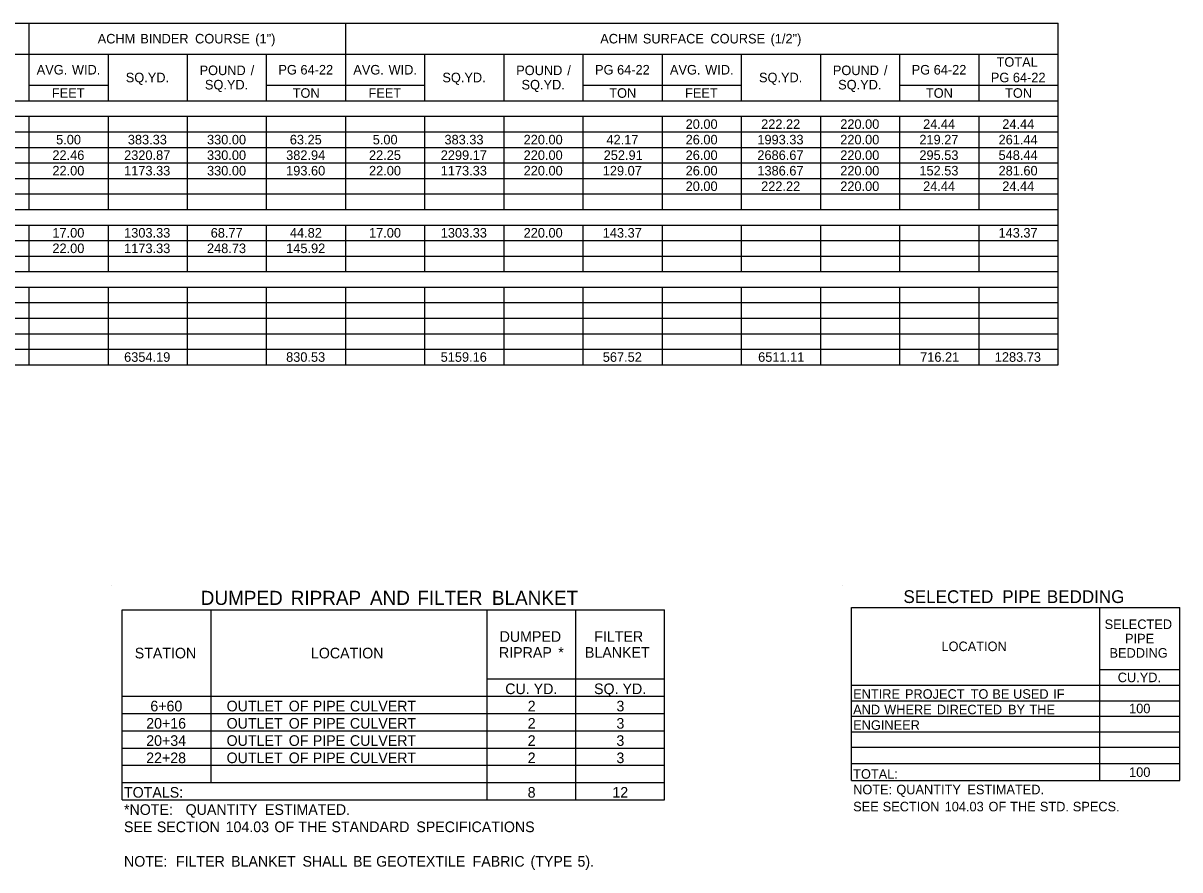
# Model space of a CAD drawing. Extents: x 1940653 to 1945779, y 534266 to 535271.
# Drawn here: x 1943159 to 1943813, y 534744 to 535222 of the extents above; entities that cross this region are included whole.
import ezdxf

# ---------------------------------------------------------------- set-up
doc = ezdxf.new("R2010")
doc.units = 0
doc.layers.add('Default', color=7, linetype='Continuous')
doc.layers.add('R_Logo', color=7, linetype='Continuous')

msp = doc.modelspace()

# ---------------------------------------------------------------- linework, layer by layer
at = {"layer": 'Default'}
for p, q in [((1942444.79, 535222.25), (1943743.93, 535222.25)), ((1943162.15, 535178.37), (1943162.15, 535222.25)), ((1943341.16, 535204.7), (1943341.16, 535222.25)), ((1943341.16, 535178.37), (1943341.16, 535222.25)), ((1943743.93, 535037.97), (1943743.93, 535222.25)), ((1943743.93, 535029.2), (1943743.93, 535222.25)), ((1942759.38, 535204.7), (1943743.93, 535204.7)), ((1943206.9, 535178.37), (1943206.9, 535204.7)), ((1943251.66, 535178.37), (1943251.66, 535204.7)), ((1943296.41, 535178.37), (1943296.41, 535204.7)), ((1943385.91, 535204.7), (1943430.67, 535204.7)), ((1943385.91, 535178.37), (1943385.91, 535204.7)), ((1943430.67, 535178.37), (1943430.67, 535204.7)), ((1943475.42, 535178.37), (1943475.42, 535204.7)), ((1943520.17, 535178.37), (1943520.17, 535204.7)), ((1943564.92, 535204.7), (1943609.68, 535204.7)), ((1943564.92, 535178.37), (1943564.92, 535204.7)), ((1943609.68, 535178.37), (1943609.68, 535204.7)), ((1943654.43, 535178.37), (1943654.43, 535204.7)), ((1943699.18, 535178.37), (1943699.18, 535204.7)), ((1943162.15, 535187.15), (1943206.9, 535187.15)), ((1943206.9, 535178.37), (1943206.9, 535187.15)), ((1943296.41, 535187.15), (1943385.91, 535187.15)), ((1943341.16, 535178.37), (1943341.16, 535187.15)), ((1943385.91, 535178.37), (1943385.91, 535187.15)), ((1943475.42, 535187.15), (1943564.92, 535187.15)), ((1943520.17, 535178.37), (1943520.17, 535187.15)), ((1943564.92, 535178.37), (1943564.92, 535187.15)), ((1943654.43, 535187.15), (1943743.93, 535187.15)), ((1942444.79, 535178.37), (1943743.93, 535178.37)), ((1943072.65, 535178.37), (1943206.9, 535178.37)), ((1943206.9, 535178.37), (1943385.91, 535178.37)), ((1943385.91, 535178.37), (1943564.92, 535178.37)), ((1943564.92, 535178.37), (1943743.93, 535178.37)), ((1942444.79, 535169.6), (1943743.93, 535169.6)), ((1943162.15, 535116.95), (1943162.15, 535169.6)), ((1943162.15, 535116.95), (1943162.15, 535169.6)), ((1943206.9, 535116.95), (1943206.9, 535169.6)), ((1943206.9, 535116.95), (1943206.9, 535169.6)), ((1943251.66, 535116.95), (1943251.66, 535169.6)), ((1943251.66, 535116.95), (1943251.66, 535169.6)), ((1943296.41, 535116.95), (1943296.41, 535169.6)), ((1943296.41, 535116.95), (1943296.41, 535169.6)), ((1943341.16, 535116.95), (1943341.16, 535169.6)), ((1943341.16, 535116.95), (1943341.16, 535169.6)), ((1943385.91, 535116.95), (1943385.91, 535169.6)), ((1943385.91, 535116.95), (1943385.91, 535169.6)), ((1943430.67, 535116.95), (1943430.67, 535169.6)), ((1943430.67, 535116.95), (1943430.67, 535169.6)), ((1943475.42, 535116.95), (1943475.42, 535169.6)), ((1943475.42, 535116.95), (1943475.42, 535169.6)), ((1943520.17, 535116.95), (1943520.17, 535169.6)), ((1943520.17, 535116.95), (1943520.17, 535169.6)), ((1943564.92, 535116.95), (1943564.92, 535169.6)), ((1943564.92, 535116.95), (1943564.92, 535169.6)), ((1943609.68, 535116.95), (1943609.68, 535169.6)), ((1943609.68, 535116.95), (1943609.68, 535169.6)), ((1943654.43, 535116.95), (1943654.43, 535169.6)), ((1943654.43, 535116.95), (1943654.43, 535169.6)), ((1943699.18, 535116.95), (1943699.18, 535169.6)), ((1943699.18, 535116.95), (1943699.18, 535169.6)), ((1942444.79, 535160.82), (1943743.93, 535160.82)), ((1942444.79, 535152.05), (1943743.93, 535152.05)), ((1942444.79, 535143.27), (1943743.93, 535143.27)), ((1942444.79, 535134.5), (1943743.93, 535134.5)), ((1942444.79, 535125.72), (1943743.93, 535125.72)), ((1942444.79, 535116.95), (1943743.93, 535116.95)), ((1943027.89, 535116.95), (1943162.15, 535116.95)), ((1943162.15, 535116.95), (1943564.92, 535116.95)), ((1943564.92, 535116.95), (1943609.68, 535116.95)), ((1943609.68, 535116.95), (1943699.18, 535116.95)), ((1943699.18, 535116.95), (1943743.93, 535116.95)), ((1942444.79, 535108.17), (1943743.93, 535108.17)), ((1943162.15, 535081.85), (1943162.15, 535108.17)), ((1943162.15, 535081.85), (1943162.15, 535108.17)), ((1943206.9, 535081.85), (1943206.9, 535108.17)), ((1943206.9, 535081.85), (1943206.9, 535108.17)), ((1943251.66, 535081.85), (1943251.66, 535108.17)), ((1943251.66, 535081.85), (1943251.66, 535108.17)), ((1943296.41, 535081.85), (1943296.41, 535108.17)), ((1943296.41, 535081.85), (1943296.41, 535108.17)), ((1943341.16, 535081.85), (1943341.16, 535108.17)), ((1943341.16, 535081.85), (1943341.16, 535108.17)), ((1943385.91, 535081.85), (1943385.91, 535108.17)), ((1943385.91, 535081.85), (1943385.91, 535108.17)), ((1943430.67, 535081.85), (1943430.67, 535108.17)), ((1943430.67, 535081.85), (1943430.67, 535108.17)), ((1943475.42, 535081.85), (1943475.42, 535108.17)), ((1943475.42, 535081.85), (1943475.42, 535108.17)), ((1943520.17, 535081.85), (1943520.17, 535108.17)), ((1943520.17, 535081.85), (1943520.17, 535108.17)), ((1943564.92, 535081.85), (1943564.92, 535108.17)), ((1943564.92, 535081.85), (1943564.92, 535108.17)), ((1943609.68, 535081.85), (1943609.68, 535108.17)), ((1943609.68, 535081.85), (1943609.68, 535108.17)), ((1943654.43, 535081.85), (1943654.43, 535108.17)), ((1943654.43, 535081.85), (1943654.43, 535108.17)), ((1943699.18, 535081.85), (1943699.18, 535108.17)), ((1943699.18, 535081.85), (1943699.18, 535108.17)), ((1942444.79, 535099.4), (1943743.93, 535099.4)), ((1942444.79, 535090.62), (1943743.93, 535090.62)), ((1942444.79, 535081.85), (1943743.93, 535081.85)), ((1943117.4, 535081.85), (1943564.92, 535081.85)), ((1943564.92, 535081.85), (1943609.68, 535081.85)), ((1943609.68, 535081.85), (1943699.18, 535081.85)), ((1943699.18, 535081.85), (1943743.93, 535081.85)), ((1942444.79, 535073.07), (1943743.93, 535073.07)), ((1943162.15, 535029.2), (1943162.15, 535073.07)), ((1943162.15, 535029.2), (1943162.15, 535073.07)), ((1943206.9, 535029.2), (1943206.9, 535073.07)), ((1943206.9, 535029.2), (1943206.9, 535073.07)), ((1943251.66, 535029.2), (1943251.66, 535073.07)), ((1943251.66, 535029.2), (1943251.66, 535073.07)), ((1943296.41, 535029.2), (1943296.41, 535073.07)), ((1943296.41, 535029.2), (1943296.41, 535073.07)), ((1943341.16, 535029.2), (1943341.16, 535073.07)), ((1943341.16, 535029.2), (1943341.16, 535073.07)), ((1943385.91, 535029.2), (1943385.91, 535073.07)), ((1943385.91, 535029.2), (1943385.91, 535073.07)), ((1943430.67, 535029.2), (1943430.67, 535073.07)), ((1943430.67, 535029.2), (1943430.67, 535073.07)), ((1943475.42, 535029.2), (1943475.42, 535073.07)), ((1943475.42, 535029.2), (1943475.42, 535073.07)), ((1943520.17, 535029.2), (1943520.17, 535073.07)), ((1943520.17, 535029.2), (1943520.17, 535073.07)), ((1943564.92, 535029.2), (1943564.92, 535073.07)), ((1943564.92, 535029.2), (1943564.92, 535073.07)), ((1943609.68, 535029.2), (1943609.68, 535073.07)), ((1943609.68, 535029.2), (1943609.68, 535073.07)), ((1943654.43, 535029.2), (1943654.43, 535073.07)), ((1943654.43, 535029.2), (1943654.43, 535073.07)), ((1943699.18, 535029.2), (1943699.18, 535073.07)), ((1943699.18, 535029.2), (1943699.18, 535073.07)), ((1942444.79, 535064.3), (1943743.93, 535064.3)), ((1942444.79, 535055.52), (1943743.93, 535055.52)), ((1942444.79, 535046.75), (1943743.93, 535046.75)), ((1942444.79, 535037.97), (1943743.93, 535037.97)), ((1942444.79, 535029.2), (1943743.93, 535029.2)), ((1943214.78, 534890.65), (1943521.42, 534890.65)), ((1943214.78, 534783.4), (1943214.78, 534890.65)), ((1943214.78, 534783.4), (1943214.78, 534890.65)), ((1943264.99, 534793.15), (1943264.99, 534890.65)), ((1943420.99, 534783.4), (1943420.99, 534890.65)), ((1943471.2, 534783.4), (1943471.2, 534890.65)), ((1943521.42, 534783.4), (1943521.42, 534890.65)), ((1943521.42, 534783.4), (1943521.42, 534890.65)), ((1943627.12, 534892.04), (1943812.71, 534892.04)), ((1943627.12, 534794.2), (1943627.12, 534892.04)), ((1943627.12, 534794.2), (1943627.12, 534892.04)), ((1943767.52, 534794.2), (1943767.52, 534892.04)), ((1943812.71, 534794.2), (1943812.71, 534892.04)), ((1943812.71, 534794.2), (1943812.71, 534892.04)), ((1943767.52, 534856.94), (1943812.71, 534856.94)), ((1943420.99, 534851.65), (1943521.42, 534851.65)), ((1943627.12, 534848.16), (1943812.71, 534848.16)), ((1943767.52, 534794.2), (1943767.52, 534848.16)), ((1943214.78, 534841.9), (1943521.42, 534841.9)), ((1943264.99, 534793.15), (1943264.99, 534841.9)), ((1943420.99, 534783.4), (1943420.99, 534841.9)), ((1943627.12, 534839.39), (1943812.71, 534839.39)), ((1943214.78, 534832.15), (1943521.42, 534832.15)), ((1943627.12, 534830.61), (1943812.71, 534830.61)), ((1943214.78, 534822.4), (1943521.42, 534822.4)), ((1943627.12, 534821.84), (1943812.71, 534821.84)), ((1943214.78, 534812.65), (1943521.42, 534812.65)), ((1943627.12, 534813.06), (1943812.71, 534813.06)), ((1943214.78, 534802.9), (1943521.42, 534802.9)), ((1943627.12, 534803.85), (1943812.71, 534803.85)), ((1943627.12, 534794.2), (1943812.71, 534794.2)), ((1943214.78, 534793.15), (1943521.42, 534793.15)), ((1943214.78, 534793.15), (1943521.42, 534793.15)), ((1943214.78, 534783.4), (1943521.42, 534783.4))]:
    msp.add_line(p, q, dxfattribs=at)
at = {"layer": 'R_Logo'}
for p, q in [((1943208.93, 534904.3), (1943208.93, 534904.3)), ((1943621.86, 534904.32), (1943621.86, 534904.32))]:
    msp.add_line(p, q, dxfattribs=at)

# ---------------------------------------------------------------- texts
at = {"layer": 'Default'}
for s, height, p in [('ACHM', 5.4, (1943200.87, 535210.77)), (' BINDER', 5.4, (1943222.96, 535210.77)), (' COURSE', 5.4, (1943253.94, 535210.77)), (' (1")', 5.4, (1943287.95, 535210.77)), ('ACHM', 5.4, (1943485.01, 535210.77)), (' SURFACE', 5.4, (1943507.1, 535210.77)), (' COURSE', 5.4, (1943545.3, 535210.77)), (' (1/2")', 5.4, (1943579.3, 535210.77)), ('TOTAL', 5.4, (1943709.1, 535197.61)), ('AVG.', 5.4, (1943166.39, 535193.22)), (' WID.', 5.4, (1943184.32, 535193.22)), ('SQ.YD.', 5.4, (1943216.75, 535188.83)), ('POUND', 5.4, (1943258.49, 535192.88)), (' /', 5.4, (1943285.37, 535192.88)), ('PG', 5.4, (1943303.06, 535193.22)), (' 64-22', 5.4, (1943313.51, 535193.22)), ('AVG.', 5.4, (1943345.4, 535193.22)), (' WID.', 5.4, (1943363.33, 535193.22)), ('SQ.YD.', 5.4, (1943395.76, 535188.83)), ('POUND', 5.4, (1943437.5, 535192.88)), (' /', 5.4, (1943464.38, 535192.88)), ('PG', 5.4, (1943482.07, 535193.22)), (' 64-22', 5.4, (1943492.52, 535193.22)), ('AVG.', 5.4, (1943524.41, 535193.22)), (' WID.', 5.4, (1943542.34, 535193.22)), ('SQ.YD.', 5.4, (1943574.77, 535188.83)), ('POUND', 5.4, (1943616.51, 535192.88)), (' /', 5.4, (1943643.39, 535192.88)), ('PG', 5.4, (1943661.08, 535193.22)), (' 64-22', 5.4, (1943671.53, 535193.22)), ('PG', 5.4, (1943705.83, 535188.83)), (' 64-22', 5.4, (1943716.28, 535188.83)), ('SQ.YD.', 5.4, (1943261.5, 535184.78)), ('SQ.YD.', 5.4, (1943440.51, 535184.78)), ('SQ.YD.', 5.4, (1943619.52, 535184.78)), ('FEET', 5.4, (1943174.96, 535180.06)), ('TON', 5.4, (1943311.12, 535180.06)), ('FEET', 5.4, (1943353.97, 535180.06)), ('TON', 5.4, (1943490.13, 535180.06)), ('FEET', 5.4, (1943532.98, 535180.06)), ('TON', 5.4, (1943669.14, 535180.06)), ('TON', 5.4, (1943713.89, 535180.06)), ('20.00', 5.4, (1943533.29, 535162.51)), ('222.22', 5.4, (1943575.97, 535162.51)), ('220.00', 5.4, (1943620.7, 535162.51)), ('24.44', 5.4, (1943667.55, 535162.51)), ('24.44', 5.4, (1943712.3, 535162.51)), ('5.00', 5.4, (1943177.37, 535153.73)), ('383.33', 5.4, (1943217.92, 535153.73)), ('330.00', 5.4, (1943262.68, 535153.73)), ('63.25', 5.4, (1943309.5, 535153.73)), ('5.00', 5.4, (1943356.38, 535153.73)), ('383.33', 5.4, (1943396.93, 535153.73)), ('220.00', 5.4, (1943441.69, 535153.73)), ('42.17', 5.4, (1943488.53, 535153.73)), ('26.00', 5.4, (1943533.29, 535153.73)), ('1993.33', 5.4, (1943573.84, 535153.73)), ('220.00', 5.4, (1943620.7, 535153.73)), ('219.27', 5.4, (1943665.44, 535153.73)), ('261.44', 5.4, (1943710.21, 535153.73)), ('22.46', 5.4, (1943175.26, 535144.96)), ('2320.87', 5.4, (1943215.82, 535144.96)), ('330.00', 5.4, (1943262.68, 535144.96)), ('382.94', 5.4, (1943307.43, 535144.96)), ('22.25', 5.4, (1943354.25, 535144.96)), ('2299.17', 5.4, (1943394.83, 535144.96)), ('220.00', 5.4, (1943441.69, 535144.96)), ('252.91', 5.4, (1943486.95, 535144.96)), ('26.00', 5.4, (1943533.29, 535144.96)), ('2686.67', 5.4, (1943573.84, 535144.96)), ('220.00', 5.4, (1943620.7, 535144.96)), ('295.53', 5.4, (1943665.44, 535144.96)), ('548.44', 5.4, (1943710.21, 535144.96)), ('22.00', 5.4, (1943175.27, 535136.18)), ('1173.33', 5.4, (1943215.82, 535136.18)), ('330.00', 5.4, (1943262.68, 535136.18)), ('193.60', 5.4, (1943307.43, 535136.18)), ('22.00', 5.4, (1943354.28, 535136.18)), ('1173.33', 5.4, (1943394.83, 535136.18)), ('220.00', 5.4, (1943441.69, 535136.18)), ('129.07', 5.4, (1943486.43, 535136.18)), ('26.00', 5.4, (1943533.29, 535136.18)), ('1386.67', 5.4, (1943573.84, 535136.18)), ('220.00', 5.4, (1943620.7, 535136.18)), ('152.53', 5.4, (1943665.44, 535136.18)), ('281.60', 5.4, (1943710.21, 535136.18)), ('20.00', 5.4, (1943533.29, 535127.41)), ('222.22', 5.4, (1943575.97, 535127.41)), ('220.00', 5.4, (1943620.7, 535127.41)), ('24.44', 5.4, (1943667.55, 535127.41)), ('24.44', 5.4, (1943712.3, 535127.41)), ('17.00', 5.4, (1943175.27, 535101.08)), ('1303.33', 5.4, (1943215.82, 535101.08)), ('68.77', 5.4, (1943264.77, 535101.08)), ('44.82', 5.4, (1943309.55, 535101.08)), ('17.00', 5.4, (1943354.28, 535101.08)), ('1303.33', 5.4, (1943394.83, 535101.08)), ('220.00', 5.4, (1943441.69, 535101.08)), ('143.37', 5.4, (1943486.43, 535101.08)), ('143.37', 5.4, (1943710.19, 535101.08)), ('22.00', 5.4, (1943175.27, 535092.31)), ('1173.33', 5.4, (1943215.82, 535092.31)), ('248.73', 5.4, (1943262.67, 535092.31)), ('145.92', 5.4, (1943307.45, 535092.31)), ('6354.19', 5.4, (1943215.82, 535030.88)), ('830.53', 5.4, (1943307.41, 535030.88)), ('5159.16', 5.4, (1943394.79, 535030.88)), ('567.52', 5.4, (1943486.45, 535030.88)), ('6511.11', 5.4, (1943574.28, 535030.88)), ('716.21', 5.4, (1943665.88, 535030.88)), ('1283.73', 5.4, (1943708.09, 535030.88)), ('DUMPED', 8, (1943259.13, 534893.48)), (' RIPRAP', 8, (1943307.02, 534893.48)), (' AND', 8, (1943351.85, 534893.48)), (' FILTER', 8, (1943378.62, 534893.48)), (' BLANKET', 8, (1943420.79, 534893.48)), ('SELECTED', 7.2, (1943656.43, 534894.58)), (' PIPE', 7.2, (1943709.6, 534894.58)), (' BEDDING', 7.2, (1943734.83, 534894.58)), ('SELECTED', 5.4, (1943770.18, 534879.89)), ('DUMPED', 6, (1943428.14, 534872.65)), ('FILTER', 6, (1943481.66, 534872.65)), ('LOCATION', 5.4, (1943677.92, 534867.4)), ('PIPE', 5.4, (1943781.71, 534871.79)), ('STATION', 6, (1943221.82, 534863.28)), ('LOCATION', 6, (1943321.44, 534863.28)), ('RIPRAP', 6, (1943427.75, 534863.65)), (' *', 6, (1943459.04, 534863.65)), ('BLANKET', 6, (1943476.37, 534863.65)), ('BEDDING', 5.4, (1943772.95, 534863.69)), ('CU.YD.', 5.4, (1943777.59, 534849.85)), ('CU.', 6, (1943431.3, 534843.1)), (' YD.', 6, (1943445.16, 534843.1)), ('SQ.', 6, (1943481.51, 534843.1)), (' YD.', 6, (1943495.38, 534843.1)), ('ENTIRE', 5.4, (1943628, 534840.47)), (' PROJECT', 5.4, (1943655.27, 534840.47)), (' TO', 5.4, (1943692.43, 534840.47)), (' BE', 5.4, (1943704.67, 534840.47)), (' USED', 5.4, (1943716.42, 534840.47)), (' IF', 5.4, (1943739.08, 534840.47)), ('6+60', 6, (1943230.65, 534833.35)), ('OUTLET', 6, (1943273.77, 534833.35)), (' OF', 6, (1943306.67, 534833.35)), (' PIPE', 6, (1943320.26, 534833.35)), (' CULVERT', 6, (1943341.24, 534833.35)), ('2', 6, (1943443.99, 534833.35)), ('3', 6, (1943494.17, 534833.35)), ('AND', 5.4, (1943628, 534831.69)), (' WHERE', 5.4, (1943643.53, 534831.69)), (' DIRECTED', 5.4, (1943673.31, 534831.69)), (' BY', 5.4, (1943713.57, 534831.69)), (' THE', 5.4, (1943725.67, 534831.69)), ('100', 5.4, (1943784.01, 534832.3)), ('20+16', 6, (1943228.31, 534823.6)), ('OUTLET', 6, (1943273.77, 534823.6)), (' OF', 6, (1943306.67, 534823.6)), (' PIPE', 6, (1943320.26, 534823.6)), (' CULVERT', 6, (1943341.24, 534823.6)), ('2', 6, (1943443.99, 534823.6)), ('3', 6, (1943494.17, 534823.6)), ('ENGINEER', 5.4, (1943628, 534822.92)), ('20+34', 6, (1943228.32, 534813.85)), ('OUTLET', 6, (1943273.77, 534813.85)), (' OF', 6, (1943306.67, 534813.85)), (' PIPE', 6, (1943320.26, 534813.85)), (' CULVERT', 6, (1943341.24, 534813.85)), ('2', 6, (1943443.99, 534813.85)), ('3', 6, (1943494.17, 534813.85)), ('22+28', 6, (1943228.3, 534804.1)), ('OUTLET', 6, (1943273.77, 534804.1)), (' OF', 6, (1943306.67, 534804.1)), (' PIPE', 6, (1943320.26, 534804.1)), (' CULVERT', 6, (1943341.24, 534804.1)), ('2', 6, (1943443.99, 534804.1)), ('3', 6, (1943494.17, 534804.1)), ('TOTAL:', 5.4, (1943628, 534795.28)), ('100', 5.4, (1943784.01, 534796.32)), ('TOTALS:', 6, (1943215.75, 534784.6)), ('8', 6, (1943443.96, 534784.6)), ('12', 6, (1943491.86, 534784.6)), ('NOTE:', 5.4, (1943628, 534786.5)), (' QUANTITY', 5.4, (1943650.4, 534786.5)), (' ESTIMATED.', 5.4, (1943690.59, 534786.5)), ('SEE', 5.4, (1943628, 534776.85)), (' SECTION', 5.4, (1943642.7, 534776.85)), (' 104.03', 5.4, (1943677.72, 534776.85)), (' OF', 5.4, (1943702.53, 534776.85)), (' THE', 5.4, (1943714.76, 534776.85)), (' STD.', 5.4, (1943731.55, 534776.85)), (' SPECS.', 5.4, (1943750.17, 534776.85)), ('*NOTE:', 6, (1943215.75, 534774.85)), ('   QUANTITY', 6, (1943243.9, 534774.85)), (' ESTIMATED.', 6, (1943293.21, 534774.85)), ('SEE', 6, (1943215.75, 534765.1)), (' SECTION', 6, (1943232.08, 534765.1)), (' 104.03', 6, (1943270.99, 534765.1)), (' OF', 6, (1943298.57, 534765.1)), (' THE', 6, (1943312.16, 534765.1)), (' STANDARD', 6, (1943330.81, 534765.1)), (' SPECIFICATIONS', 6, (1943378.81, 534765.1)), ('NOTE:', 6, (1943215.75, 534745.6)), ('  FILTER', 6, (1943240.64, 534745.6)), (' BLANKET', 6, (1943274.06, 534745.6)), (' SHALL', 6, (1943314.43, 534745.6)), (' BE', 6, (1943343.02, 534745.6)), (' GEOTEXTILE', 6, (1943356.09, 534745.6)), (' FABRIC', 6, (1943410.61, 534745.6)), (' (TYPE', 6, (1943443.35, 534745.6)), (' 5).', 6, (1943469.92, 534745.6))]:
    msp.add_text(s, height=height, dxfattribs=at).set_placement(p)

doc.saveas('drawing.dxf')
